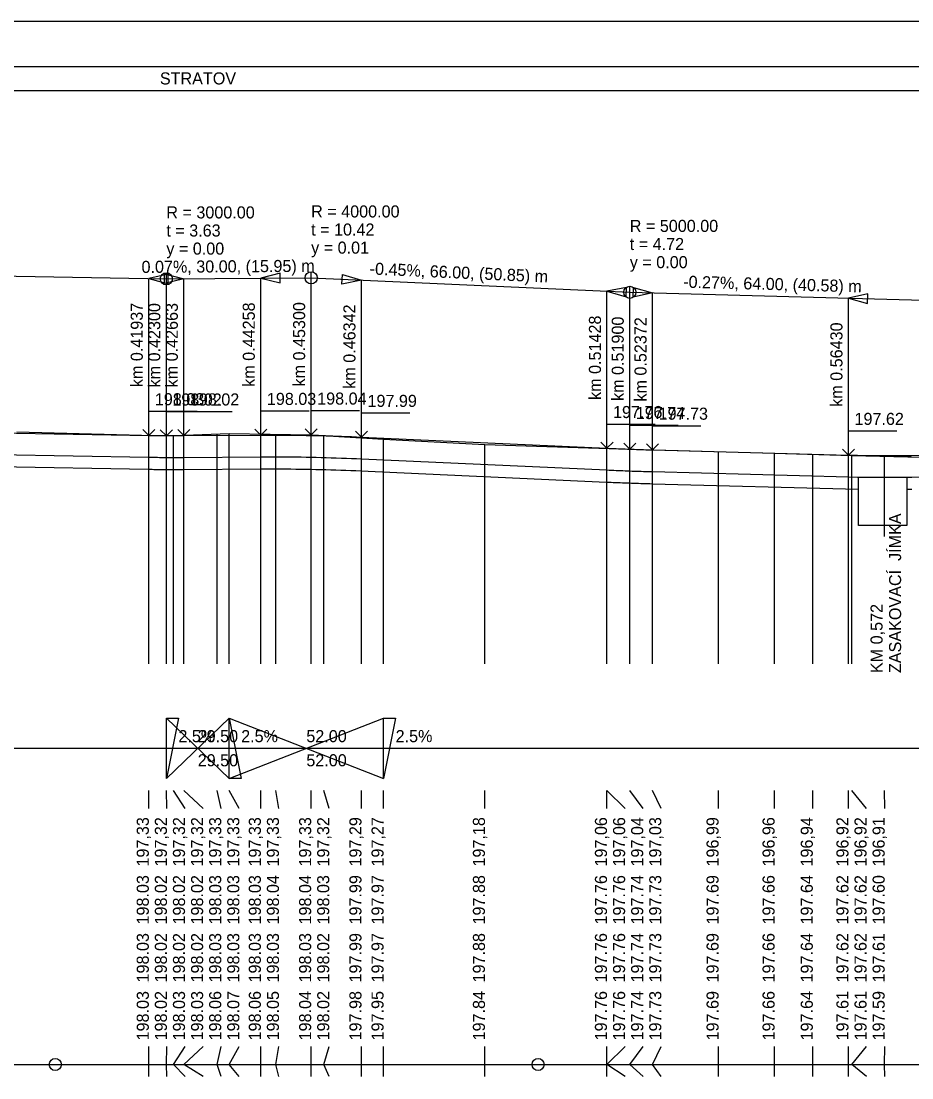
# Model space of a CAD drawing. Extents: x -51 to 53, y -74 to 15.
# Drawn here: x 0.85 to 19.3, y -6.73 to 15.15 of the extents above; entities that cross this region are included whole.
import ezdxf

# ---------------------------------------------------------------- set-up
doc = ezdxf.new("R2010")
doc.units = 0
for name, color, linetype in [('Implicitní', 7, 'Continuous'), ('KONSTRUKCE_L', 7, 'Continuous'), ('KOTY_L', 7, 'Continuous'), ('KOTY_N', 7, 'Continuous'), ('KOTY_S', 7, 'Continuous'), ('KOTY_T', 7, 'Continuous'), ('KOTY_VP', 7, 'Continuous'), ('LEGENDA', 7, 'Continuous'), ('Nová vrstva (0)', 7, 'Continuous'), ('PR_SKLON_L', 7, 'Continuous'), ('PR_SKLON_T', 7, 'Continuous'), ('ROVINA_L', 7, 'Continuous'), ('ROVINA_O', 7, 'Continuous'), ('SKLON_POMERY', 7, 'Continuous'), ('TABULKY_L', 7, 'Continuous'), ('TEREN_L', 7, 'Continuous'), ('V_POLYGON', 7, 'Continuous'), ('V_POLYGON_ZO', 7, 'Continuous')]:
    doc.layers.add(name, color=color, linetype=linetype)

msp = doc.modelspace()

# ---------------------------------------------------------------- linework, layer by layer
at = {"layer": 'Implicitní'}
msp.add_lwpolyline([(-51.392, 15.154), (53.079, 15.154), (53.079, -14.546), (-51.392, -14.546)], close=True, dxfattribs=at)
at = {"layer": 'KONSTRUKCE_L'}
for p, q in [((-4.872, 6.272), (3.497, 6.125)), ((4.223, 6.121), (5.818, 6.132)), ((5.818, 6.132), (5.922, 6.132)), ((5.922, 6.132), (6.026, 6.133)), ((6.026, 6.133), (6.13, 6.133)), ((6.13, 6.133), (6.235, 6.132)), ((6.235, 6.132), (6.339, 6.132)), ((6.339, 6.132), (6.443, 6.131)), ((6.443, 6.131), (6.547, 6.13)), ((6.547, 6.13), (6.652, 6.129)), ((6.652, 6.129), (6.756, 6.127)), ((6.756, 6.127), (6.86, 6.125)), ((3.497, 6.125), (3.533, 6.125)), ((3.533, 6.125), (3.57, 6.124)), ((3.57, 6.124), (3.606, 6.123)), ((3.606, 6.123), (3.642, 6.123)), ((3.642, 6.123), (3.679, 6.123)), ((3.679, 6.123), (3.715, 6.122)), ((3.715, 6.122), (3.751, 6.122)), ((3.751, 6.122), (3.787, 6.121)), ((3.787, 6.121), (3.824, 6.121)), ((3.824, 6.121), (3.86, 6.121)), ((3.86, 6.121), (3.896, 6.121)), ((3.896, 6.121), (3.933, 6.121)), ((3.933, 6.121), (3.969, 6.121)), ((3.969, 6.121), (4.005, 6.121)), ((4.005, 6.121), (4.041, 6.121)), ((4.041, 6.121), (4.078, 6.121)), ((4.078, 6.121), (4.114, 6.121)), ((4.114, 6.121), (4.15, 6.121)), ((4.15, 6.121), (4.187, 6.121)), ((4.187, 6.121), (4.223, 6.121)), ((6.86, 6.125), (6.964, 6.123)), ((6.964, 6.123), (7.068, 6.121)), ((7.068, 6.121), (7.173, 6.118)), ((7.173, 6.118), (7.277, 6.115)), ((7.277, 6.115), (7.381, 6.112)), ((7.381, 6.112), (7.485, 6.108)), ((7.485, 6.108), (7.59, 6.104)), ((7.59, 6.104), (7.694, 6.1)), ((7.694, 6.1), (7.798, 6.096)), ((7.798, 6.096), (7.902, 6.091)), ((7.902, 6.091), (12.988, 5.86)), ((12.988, 5.86), (13.035, 5.858)), ((13.035, 5.858), (13.082, 5.856)), ((13.082, 5.856), (13.129, 5.854)), ((13.129, 5.854), (13.177, 5.852)), ((13.177, 5.852), (13.224, 5.85)), ((13.224, 5.85), (13.271, 5.848)), ((13.271, 5.848), (13.318, 5.846)), ((13.318, 5.846), (13.366, 5.845)), ((13.366, 5.845), (13.413, 5.843)), ((13.413, 5.843), (13.46, 5.841)), ((13.46, 5.841), (13.507, 5.839)), ((13.507, 5.839), (13.554, 5.838)), ((13.554, 5.838), (13.602, 5.836)), ((13.602, 5.836), (13.649, 5.835)), ((13.649, 5.835), (13.696, 5.833)), ((13.696, 5.833), (13.743, 5.832)), ((13.743, 5.832), (13.791, 5.83)), ((13.791, 5.83), (13.838, 5.829)), ((13.838, 5.829), (13.885, 5.828)), ((13.885, 5.828), (13.932, 5.826)), ((13.932, 5.826), (17.99, 5.718)), ((17.99, 5.718), (18.177, 5.714)), ((18.177, 5.714), (18.364, 5.711)), ((18.364, 5.711), (18.551, 5.709)), ((18.551, 5.709), (18.738, 5.708)), ((18.738, 5.708), (18.925, 5.708)), ((18.925, 5.708), (19.112, 5.71)), ((19.112, 5.71), (19.299, 5.712)), ((19.299, 5.712), (19.486, 5.716))]:
    msp.add_line(p, q, dxfattribs=at)
at = {"layer": 'KOTY_L'}
for p, q in [((3.497, 1.849), (3.497, 6.578)), ((3.86, 1.849), (3.86, 6.569)), ((4.005, 1.849), (4.005, 6.574)), ((4.223, 1.849), (4.223, 6.583)), ((4.91, 1.849), (4.91, 6.609)), ((5.16, 1.849), (5.16, 6.619)), ((5.818, 1.849), (5.818, 6.607)), ((6.13, 1.849), (6.13, 6.602)), ((6.86, 1.849), (6.86, 6.589)), ((7.119, 1.849), (7.119, 6.573)), ((7.902, 1.849), (7.902, 6.526)), ((8.36, 1.849), (8.36, 6.499)), ((10.46, 1.849), (10.46, 6.389)), ((12.988, 1.849), (12.988, 6.305)), ((12.988, 1.849), (12.988, 6.305)), ((13.46, 1.849), (13.46, 6.289)), ((13.932, 1.849), (13.932, 6.276)), ((15.3, 1.849), (15.3, 6.24)), ((16.46, 1.849), (16.46, 6.209)), ((17.251, 1.849), (17.251, 6.184)), ((17.99, 1.849), (17.99, 6.161)), ((18.06, 1.849), (18.06, 6.159)), ((18.738, 4.481), (18.738, 6.144)), ((3.497, -1.151), (3.497, -0.776)), ((3.872, -1.151), (3.86, -0.776)), ((4.247, -1.151), (4.005, -0.776)), ((4.622, -1.151), (4.223, -0.776)), ((4.997, -1.151), (4.91, -0.776)), ((5.372, -1.151), (5.16, -0.776)), ((5.818, -1.151), (5.818, -0.776)), ((6.193, -1.151), (6.13, -0.776)), ((6.86, -1.151), (6.86, -0.776)), ((7.235, -1.151), (7.119, -0.776)), ((7.902, -1.151), (7.902, -0.776)), ((8.36, -1.151), (8.36, -0.776)), ((10.46, -1.151), (10.46, -0.776)), ((12.988, -1.151), (12.988, -0.776)), ((13.363, -1.151), (12.988, -0.776)), ((13.738, -1.151), (13.46, -0.776)), ((14.113, -1.151), (13.932, -0.776)), ((15.3, -1.151), (15.3, -0.776)), ((16.46, -1.151), (16.46, -0.776)), ((17.251, -1.151), (17.251, -0.776)), ((17.99, -1.151), (17.99, -0.776)), ((18.365, -1.151), (18.06, -0.776)), ((18.74, -1.151), (18.738, -0.776)), ((3.497, -4.751), (3.497, -4.751)), ((3.872, -4.751), (3.872, -4.751)), ((4.247, -4.751), (4.247, -4.751)), ((4.622, -4.751), (4.622, -4.751)), ((4.997, -4.751), (4.997, -4.751)), ((5.372, -4.751), (5.372, -4.751)), ((5.818, -4.751), (5.818, -4.751)), ((6.193, -4.751), (6.193, -4.751)), ((6.86, -4.751), (6.86, -4.751)), ((7.235, -4.751), (7.235, -4.751)), ((7.902, -4.751), (7.902, -4.751)), ((8.36, -4.751), (8.36, -4.751)), ((10.46, -4.751), (10.46, -4.751)), ((12.988, -4.751), (12.988, -4.751)), ((13.363, -4.751), (13.363, -4.751)), ((13.738, -4.751), (13.738, -4.751)), ((14.113, -4.751), (14.113, -4.751)), ((15.3, -4.751), (15.3, -4.751)), ((16.46, -4.751), (16.46, -4.751)), ((17.251, -4.751), (17.251, -4.751)), ((17.99, -4.751), (17.99, -4.751)), ((18.365, -4.751), (18.365, -4.751)), ((18.74, -4.751), (18.74, -4.751)), ((3.497, -6.451), (3.497, -6.076)), ((3.86, -6.451), (3.872, -6.076)), ((4.005, -6.451), (4.247, -6.076)), ((4.223, -6.451), (4.622, -6.076)), ((4.91, -6.451), (4.997, -6.076)), ((5.16, -6.451), (5.372, -6.076)), ((5.818, -6.451), (5.818, -6.076)), ((6.13, -6.451), (6.193, -6.076)), ((6.86, -6.451), (6.86, -6.076)), ((7.119, -6.451), (7.235, -6.076)), ((7.902, -6.451), (7.902, -6.076)), ((8.36, -6.451), (8.36, -6.076)), ((10.46, -6.451), (10.46, -6.076)), ((12.988, -6.451), (12.988, -6.076)), ((12.988, -6.451), (13.363, -6.076)), ((13.46, -6.451), (13.738, -6.076)), ((13.932, -6.451), (14.113, -6.076)), ((15.3, -6.451), (15.3, -6.076)), ((16.46, -6.451), (16.46, -6.076)), ((17.251, -6.451), (17.251, -6.076)), ((17.99, -6.451), (17.99, -6.076)), ((18.06, -6.451), (18.365, -6.076)), ((18.738, -6.451), (18.74, -6.076))]:
    msp.add_line(p, q, dxfattribs=at)
at = {"layer": 'KOTY_S'}
for p, q in [((3.497, -6.701), (3.497, -6.451)), ((3.872, -6.701), (3.86, -6.451)), ((4.247, -6.701), (4.005, -6.451)), ((4.622, -6.701), (4.223, -6.451)), ((4.997, -6.701), (4.91, -6.451)), ((5.372, -6.701), (5.16, -6.451)), ((5.818, -6.701), (5.818, -6.451)), ((6.193, -6.701), (6.13, -6.451)), ((6.86, -6.701), (6.86, -6.451)), ((7.235, -6.701), (7.119, -6.451)), ((7.902, -6.701), (7.902, -6.451)), ((8.36, -6.701), (8.36, -6.451)), ((10.46, -6.701), (10.46, -6.451)), ((12.988, -6.701), (12.988, -6.451)), ((13.363, -6.701), (12.988, -6.451)), ((13.738, -6.701), (13.46, -6.451)), ((14.113, -6.701), (13.932, -6.451)), ((15.3, -6.701), (15.3, -6.451)), ((16.46, -6.701), (16.46, -6.451)), ((17.251, -6.701), (17.251, -6.451)), ((17.99, -6.701), (17.99, -6.451)), ((18.365, -6.701), (18.06, -6.451)), ((18.74, -6.701), (18.738, -6.451))]:
    msp.add_line(p, q, dxfattribs=at)
at = {"layer": 'Nová vrstva (0)'}
for p, q in [((-4.877, 6.022), (3.493, 5.875)), ((3.493, 5.875), (3.529, 5.875)), ((3.529, 5.875), (3.566, 5.874)), ((3.566, 5.874), (3.602, 5.873)), ((3.603, 5.873), (3.639, 5.873)), ((3.639, 5.873), (3.676, 5.873)), ((3.676, 5.873), (3.712, 5.872)), ((3.712, 5.872), (3.749, 5.872)), ((3.749, 5.872), (3.785, 5.871)), ((3.786, 5.871), (3.822, 5.871)), ((3.822, 5.871), (3.858, 5.871)), ((3.859, 5.871), (3.895, 5.871)), ((3.895, 5.871), (3.932, 5.871)), ((3.932, 5.871), (3.968, 5.871)), ((3.969, 5.871), (4.005, 5.871)), ((4.005, 5.871), (4.041, 5.871)), ((4.042, 5.871), (4.078, 5.871)), ((4.078, 5.871), (4.115, 5.871)), ((4.115, 5.871), (4.151, 5.871)), ((4.152, 5.871), (4.188, 5.871)), ((4.188, 5.871), (4.224, 5.871)), ((4.225, 5.871), (5.819, 5.882)), ((5.819, 5.882), (5.923, 5.882)), ((5.923, 5.882), (6.027, 5.883)), ((6.026, 5.883), (6.13, 5.883)), ((6.13, 5.883), (6.234, 5.882)), ((6.233, 5.882), (6.338, 5.882)), ((6.337, 5.882), (6.441, 5.881)), ((6.44, 5.881), (6.545, 5.88)), ((6.544, 5.88), (6.648, 5.879)), ((6.648, 5.879), (6.752, 5.877)), ((6.751, 5.877), (6.855, 5.875)), ((6.855, 5.875), (6.959, 5.873)), ((6.958, 5.873), (7.063, 5.871)), ((7.062, 5.871), (7.166, 5.868)), ((7.166, 5.868), (7.27, 5.865)), ((7.269, 5.865), (7.373, 5.862)), ((7.373, 5.862), (7.477, 5.858)), ((7.476, 5.858), (7.581, 5.855)), ((7.58, 5.855), (7.684, 5.851)), ((7.684, 5.851), (7.788, 5.846)), ((7.787, 5.846), (7.891, 5.842)), ((7.891, 5.842), (12.976, 5.611)), ((12.976, 5.611), (13.024, 5.608)), ((13.024, 5.608), (13.071, 5.606)), ((13.071, 5.606), (13.119, 5.604)), ((13.119, 5.604), (13.166, 5.602)), ((13.166, 5.602), (13.214, 5.6)), ((13.214, 5.6), (13.261, 5.598)), ((13.261, 5.598), (13.308, 5.597)), ((13.309, 5.597), (13.356, 5.595)), ((13.356, 5.595), (13.403, 5.593)), ((13.404, 5.593), (13.451, 5.591)), ((13.451, 5.591), (13.498, 5.59)), ((13.499, 5.59), (13.546, 5.588)), ((13.546, 5.588), (13.593, 5.586)), ((13.594, 5.586), (13.641, 5.585)), ((13.641, 5.585), (13.688, 5.583)), ((13.688, 5.583), (13.736, 5.582)), ((13.736, 5.582), (13.783, 5.58)), ((13.783, 5.58), (13.831, 5.579)), ((13.831, 5.579), (13.878, 5.578)), ((13.878, 5.578), (13.926, 5.576)), ((13.926, 5.576), (18.198, 5.463)), ((19.189, 5.461), (19.302, 5.462))]:
    msp.add_line(p, q, dxfattribs=at)
msp.add_lwpolyline([(18.198, 5.708), (19.198, 5.708), (19.198, 4.708), (18.198, 4.708)], close=True, dxfattribs=at)
at = {"layer": 'PR_SKLON_L'}
for p, q in [((3.86, -0.526), (5.16, 0.724)), ((3.86, 0.724), (5.16, -0.526)), ((5.16, -0.526), (8.36, 0.724)), ((5.16, 0.724), (8.36, -0.526)), ((-5.84, 0.099), (3.86, 0.099)), ((3.86, 0.099), (5.16, 0.099)), ((5.16, 0.099), (8.36, 0.099)), ((8.36, 0.099), (50.86, 0.099)), ((5.16, -0.526), (5.16, -0.526)), ((8.36, -0.526), (8.36, -0.526))]:
    msp.add_line(p, q, dxfattribs=at)
for points in [[(3.86, 0.099), (3.86, 0.724), (4.11, 0.724), (3.86, -0.526)], [(5.16, 0.099), (5.16, 0.724), (5.41, -0.526), (5.16, -0.526)], [(8.36, 0.099), (8.36, 0.724), (8.61, 0.724), (8.36, -0.526)]]:
    msp.add_lwpolyline(points, close=True, dxfattribs=at)
at = {"layer": 'ROVINA_L'}
msp.add_line((-38.44, -6.451), (50.86, -6.451), dxfattribs=at)
at = {"layer": 'ROVINA_O'}
for centre in [(1.56, -6.451), (11.56, -6.451)]:
    msp.add_circle(centre, 0.125, dxfattribs=at)
at = {"layer": 'SKLON_POMERY'}
for p, q in [((-5.84, 9.989), (3.86, 9.819)), ((3.86, 9.819), (3.86, 9.944)), ((6.86, 9.839), (6.86, 9.964)), ((3.497, 6.575), (3.497, 9.825)), ((3.86, 9.819), (6.86, 9.839)), ((3.86, 6.569), (3.86, 9.819)), ((4.223, 6.571), (4.223, 9.821)), ((5.818, 6.582), (5.818, 9.832)), ((6.86, 6.589), (6.86, 9.839)), ((6.86, 9.839), (13.46, 9.539)), ((7.902, 6.541), (7.902, 9.791)), ((13.46, 9.539), (13.46, 9.664)), ((12.988, 6.31), (12.988, 9.56)), ((13.46, 6.289), (13.46, 9.539)), ((13.46, 9.539), (19.86, 9.369)), ((13.932, 6.276), (13.932, 9.526)), ((17.99, 6.168), (17.99, 9.418))]:
    msp.add_line(p, q, dxfattribs=at)
for points in [[(3.497, 9.825), (3.895, 9.718), (3.899, 9.918), (3.497, 9.825)], [(4.223, 9.821), (3.824, 9.719), (3.822, 9.919), (4.223, 9.821)], [(5.818, 9.832), (6.218, 9.735), (6.217, 9.935), (5.818, 9.832)], [(7.902, 9.791), (7.498, 9.71), (7.507, 9.909), (7.902, 9.791)], [(12.988, 9.56), (13.383, 9.442), (13.392, 9.642), (12.988, 9.56)], [(13.932, 9.526), (13.53, 9.437), (13.535, 9.637), (13.932, 9.526)], [(17.99, 9.418), (18.387, 9.308), (18.392, 9.508), (17.99, 9.418)]]:
    msp.add_lwpolyline(points, close=True, dxfattribs=at)
for points in [[(3.372, 6.7), (3.497, 6.575), (3.622, 6.7), (3.497, 6.575), (3.497, 7.075), (4.497, 7.075)], [(3.735, 6.694), (3.86, 6.569), (3.985, 6.694), (3.86, 6.569), (3.86, 7.069), (4.86, 7.069)], [(4.098, 6.696), (4.223, 6.571), (4.348, 6.696), (4.223, 6.571), (4.223, 7.071), (5.223, 7.071)], [(5.693, 6.707), (5.818, 6.582), (5.943, 6.707), (5.818, 6.582), (5.818, 7.082), (6.818, 7.082)], [(6.735, 6.714), (6.86, 6.589), (6.985, 6.714), (6.86, 6.589), (6.86, 7.089), (7.86, 7.089)], [(7.777, 6.666), (7.902, 6.541), (8.027, 6.666), (7.902, 6.541), (7.902, 7.041), (8.902, 7.041)], [(12.863, 6.435), (12.988, 6.31), (13.113, 6.435), (12.988, 6.31), (12.988, 6.81), (13.988, 6.81)], [(13.335, 6.414), (13.46, 6.289), (13.585, 6.414), (13.46, 6.289), (13.46, 6.789), (14.46, 6.789)], [(13.807, 6.401), (13.932, 6.276), (14.057, 6.401), (13.932, 6.276), (13.932, 6.776), (14.932, 6.776)], [(17.865, 6.293), (17.99, 6.168), (18.115, 6.293), (17.99, 6.168), (17.99, 6.668), (18.99, 6.668)]]:
    msp.add_lwpolyline(points, dxfattribs=at)
for centre in [(3.86, 9.819), (6.86, 9.839), (13.46, 9.539)]:
    msp.add_circle(centre, 0.125, dxfattribs=at)
at = {"layer": 'TABULKY_L'}
for p, q in [((-38.44, 14.218), (50.86, 14.218)), ((-38.44, 13.718), (50.86, 13.718))]:
    msp.add_line(p, q, dxfattribs=at)
at = {"layer": 'TEREN_L'}
for p, q in [((0.76, 6.649), (3.86, 6.569)), ((3.86, 6.569), (5.16, 6.619)), ((5.16, 6.619), (6.86, 6.589)), ((6.86, 6.589), (8.36, 6.499)), ((8.36, 6.499), (10.46, 6.389)), ((10.46, 6.389), (13.46, 6.289)), ((13.46, 6.289), (16.46, 6.209)), ((16.46, 6.209), (18.06, 6.159)), ((18.06, 6.159), (19.86, 6.119))]:
    msp.add_line(p, q, dxfattribs=at)
at = {"layer": 'V_POLYGON'}
for p, q in [((-4.872, 6.722), (3.497, 6.575)), ((4.223, 6.571), (5.818, 6.582)), ((7.902, 6.541), (12.988, 6.31)), ((13.932, 6.276), (17.99, 6.168))]:
    msp.add_line(p, q, dxfattribs=at)
for points in [[(3.497, 6.575), (3.533, 6.575), (3.57, 6.574), (3.606, 6.573), (3.642, 6.573), (3.679, 6.573), (3.715, 6.572), (3.751, 6.572), (3.787, 6.571), (3.824, 6.571), (3.86, 6.571), (3.896, 6.571), (3.933, 6.571), (3.969, 6.571), (4.005, 6.571), (4.041, 6.571), (4.078, 6.571), (4.114, 6.571), (4.15, 6.571), (4.187, 6.571), (4.223, 6.571)], [(5.818, 6.582), (5.922, 6.582), (6.026, 6.583), (6.13, 6.583), (6.235, 6.582), (6.339, 6.582), (6.443, 6.581), (6.547, 6.58), (6.652, 6.579), (6.756, 6.577), (6.86, 6.575), (6.964, 6.573), (7.068, 6.571), (7.173, 6.568), (7.277, 6.565), (7.381, 6.562), (7.485, 6.558), (7.59, 6.554), (7.694, 6.55), (7.798, 6.546), (7.902, 6.541)], [(12.988, 6.31), (13.035, 6.308), (13.082, 6.306), (13.129, 6.304), (13.177, 6.302), (13.224, 6.3), (13.271, 6.298), (13.318, 6.296), (13.366, 6.295), (13.413, 6.293), (13.46, 6.291), (13.507, 6.289), (13.554, 6.288), (13.602, 6.286), (13.649, 6.285), (13.696, 6.283), (13.743, 6.282), (13.791, 6.28), (13.838, 6.279), (13.885, 6.278), (13.932, 6.276)], [(17.99, 6.168), (18.177, 6.164), (18.364, 6.161), (18.551, 6.159), (18.738, 6.158), (18.925, 6.158), (19.112, 6.16), (19.299, 6.162), (19.486, 6.166), (19.673, 6.171), (19.86, 6.177), (20.047, 6.184), (20.234, 6.193), (20.421, 6.202), (20.608, 6.213), (20.795, 6.225), (20.982, 6.238), (21.169, 6.253), (21.356, 6.268), (21.543, 6.285), (21.73, 6.302)]]:
    msp.add_lwpolyline(points, dxfattribs=at)
at = {"layer": 'V_POLYGON_ZO'}
for p, q in [((3.497, 6.575), (3.86, 6.569)), ((3.86, 6.569), (4.223, 6.571)), ((5.818, 6.582), (6.86, 6.589)), ((6.86, 6.589), (7.902, 6.541)), ((12.988, 6.31), (13.46, 6.289)), ((13.46, 6.289), (13.932, 6.276)), ((17.99, 6.168), (19.86, 6.119))]:
    msp.add_line(p, q, dxfattribs=at)

# ---------------------------------------------------------------- texts
at = {"layer": 'KOTY_N'}
for s, p in [('198.03', (3.497, -4.751)), ('198.02', (3.872, -4.751)), ('198.02', (4.247, -4.751)), ('198.02', (4.622, -4.751)), ('198.03', (4.997, -4.751)), ('198.03', (5.372, -4.751)), ('198.03', (5.818, -4.751)), ('198.03', (6.193, -4.751)), ('198.03', (6.86, -4.751)), ('198.02', (7.235, -4.751)), ('197.99', (7.902, -4.751)), ('197.97', (8.36, -4.751)), ('197.88', (10.46, -4.751)), ('197.76', (12.988, -4.751)), ('197.76', (13.363, -4.751)), ('197.74', (13.738, -4.751)), ('197.73', (14.113, -4.751)), ('197.69', (15.3, -4.751)), ('197.66', (16.46, -4.751)), ('197.64', (17.251, -4.751)), ('197.62', (17.99, -4.751)), ('197.62', (18.365, -4.751)), ('197.61', (18.74, -4.751))]:
    msp.add_text(s, height=0.25, rotation=90, dxfattribs=at).set_placement(p)
at = {"layer": 'KOTY_T'}
for s, p in [('198.03', (3.497, -5.951)), ('198.02', (3.872, -5.951)), ('198.03', (4.247, -5.951)), ('198.03', (4.622, -5.951)), ('198.06', (4.997, -5.951)), ('198.07', (5.372, -5.951)), ('198.06', (5.818, -5.951)), ('198.05', (6.193, -5.951)), ('198.04', (6.86, -5.951)), ('198.02', (7.235, -5.951)), ('197.98', (7.902, -5.951)), ('197.95', (8.36, -5.951)), ('197.84', (10.46, -5.951)), ('197.76', (12.988, -5.951)), ('197.76', (13.363, -5.951)), ('197.74', (13.738, -5.951)), ('197.73', (14.113, -5.951)), ('197.69', (15.3, -5.951)), ('197.66', (16.46, -5.951)), ('197.64', (17.251, -5.951)), ('197.61', (17.99, -5.951)), ('197.61', (18.365, -5.951)), ('197.59', (18.74, -5.951))]:
    msp.add_text(s, height=0.25, rotation=90, dxfattribs=at).set_placement(p)
at = {"layer": 'KOTY_VP'}
for s, p in [('198.03', (3.497, -3.551)), ('198.02', (3.872, -3.551)), ('198.02', (4.247, -3.551)), ('198.02', (4.622, -3.551)), ('198.03', (4.997, -3.551)), ('198.03', (5.372, -3.551)), ('198.03', (5.818, -3.551)), ('198.04', (6.193, -3.551)), ('198.04', (6.86, -3.551)), ('198.03', (7.235, -3.551)), ('197.99', (7.902, -3.551)), ('197.97', (8.36, -3.551)), ('197.88', (10.46, -3.551)), ('197.76', (12.988, -3.551)), ('197.76', (13.363, -3.551)), ('197.74', (13.738, -3.551)), ('197.73', (14.113, -3.551)), ('197.69', (15.3, -3.551)), ('197.66', (16.46, -3.551)), ('197.64', (17.251, -3.551)), ('197.62', (17.99, -3.551)), ('197.62', (18.365, -3.551)), ('197.60', (18.74, -3.551))]:
    msp.add_text(s, height=0.25, rotation=90, dxfattribs=at).set_placement(p)
at = {"layer": 'LEGENDA'}
msp.add_text('STRATOV', height=0.25, dxfattribs=at).set_placement((3.726, 13.843))
at = {"layer": 'Nová vrstva (0)'}
for s, p in [('ZASAKOVACÍ  JÍMKA', (19.081, 1.655)), ('KM 0,572', (18.697, 1.655)), ('197,33', (3.497, -2.351)), ('197,32', (3.872, -2.351)), ('197,32', (4.247, -2.351)), ('197,32', (4.622, -2.351)), ('197,33', (4.997, -2.351)), ('197,33', (5.372, -2.351)), ('197,33', (5.818, -2.351)), ('197,33', (6.193, -2.351)), ('197,33', (6.86, -2.351)), ('197,32', (7.235, -2.351)), ('197,29', (7.902, -2.351)), ('197,27', (8.36, -2.351)), ('197,18', (10.46, -2.351)), ('197,06', (12.988, -2.351)), ('197,06', (13.363, -2.351)), ('197,04', (13.738, -2.351)), ('197,03', (14.113, -2.351)), ('196,99', (15.3, -2.351)), ('196,96', (16.46, -2.351)), ('196,94', (17.251, -2.351)), ('196,92', (17.99, -2.351)), ('196,92', (18.365, -2.351)), ('196,91', (18.74, -2.351))]:
    msp.add_text(s, height=0.25, rotation=90, dxfattribs=at).set_placement(p)
at = {"layer": 'PR_SKLON_T'}
for s, p in [('2.5%', (4.11, 0.224)), ('29.50', (4.51, 0.224)), ('2.5%', (5.41, 0.224)), ('52.00', (6.76, 0.224)), ('2.5%', (8.61, 0.224)), ('29.50', (4.51, -0.276)), ('52.00', (6.76, -0.276))]:
    msp.add_text(s, height=0.25, dxfattribs=at).set_placement(p)
at = {"layer": 'SKLON_POMERY'}
for s, p in [('R = 3000.00', (3.86, 11.069)), ('R = 4000.00', (6.86, 11.089)), ('t = 3.63', (3.86, 10.694)), ('t = 10.42', (6.86, 10.714)), ('R = 5000.00', (13.46, 10.789)), ('y = 0.00', (3.86, 10.319)), ('y = 0.01', (6.86, 10.339)), ('t = 4.72', (13.46, 10.414)), ('y = 0.00', (13.46, 10.039)), ('198.03', (3.622, 7.2)), ('198.02', (3.985, 7.194)), ('198.02', (4.348, 7.196)), ('198.03', (5.943, 7.207)), ('198.04', (6.985, 7.214)), ('197.99', (8.027, 7.166)), ('197.76', (13.113, 6.935)), ('197.74', (13.585, 6.914)), ('197.73', (14.057, 6.901)), ('197.62', (18.115, 6.793))]:
    msp.add_text(s, height=0.25, dxfattribs=at).set_placement(p)
for s, rotation, p in [('0.07%, 30.00, (15.95) m', 0.382, (3.347, 9.94)), ('-0.45%, 66.00, (50.85) m', 357.3975, (8.068, 9.909)), ('-0.27%, 64.00, (40.58) m', 358.4785, (14.564, 9.635)), ('km 0.41937', 90, (3.372, 7.575)), ('km 0.42300', 90, (3.735, 7.569)), ('km 0.42663', 90, (4.098, 7.571)), ('km 0.44258', 90, (5.693, 7.582)), ('km 0.45300', 90, (6.735, 7.589)), ('km 0.46342', 90, (7.777, 7.541)), ('km 0.51428', 90, (12.863, 7.31)), ('km 0.51900', 90, (13.335, 7.289)), ('km 0.52372', 90, (13.807, 7.276)), ('km 0.56430', 90, (17.865, 7.168))]:
    msp.add_text(s, height=0.25, rotation=rotation, dxfattribs=at).set_placement(p)

doc.saveas('drawing.dxf')
